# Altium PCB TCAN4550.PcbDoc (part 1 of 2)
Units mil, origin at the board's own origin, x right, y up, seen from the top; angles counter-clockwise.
Board outline 2000 x 1600 mil, 2 copper layers (Top Layer, Bottom Layer), stack 62 mil thick; 83 components, 51 nets, 217 pads, 26 vias.
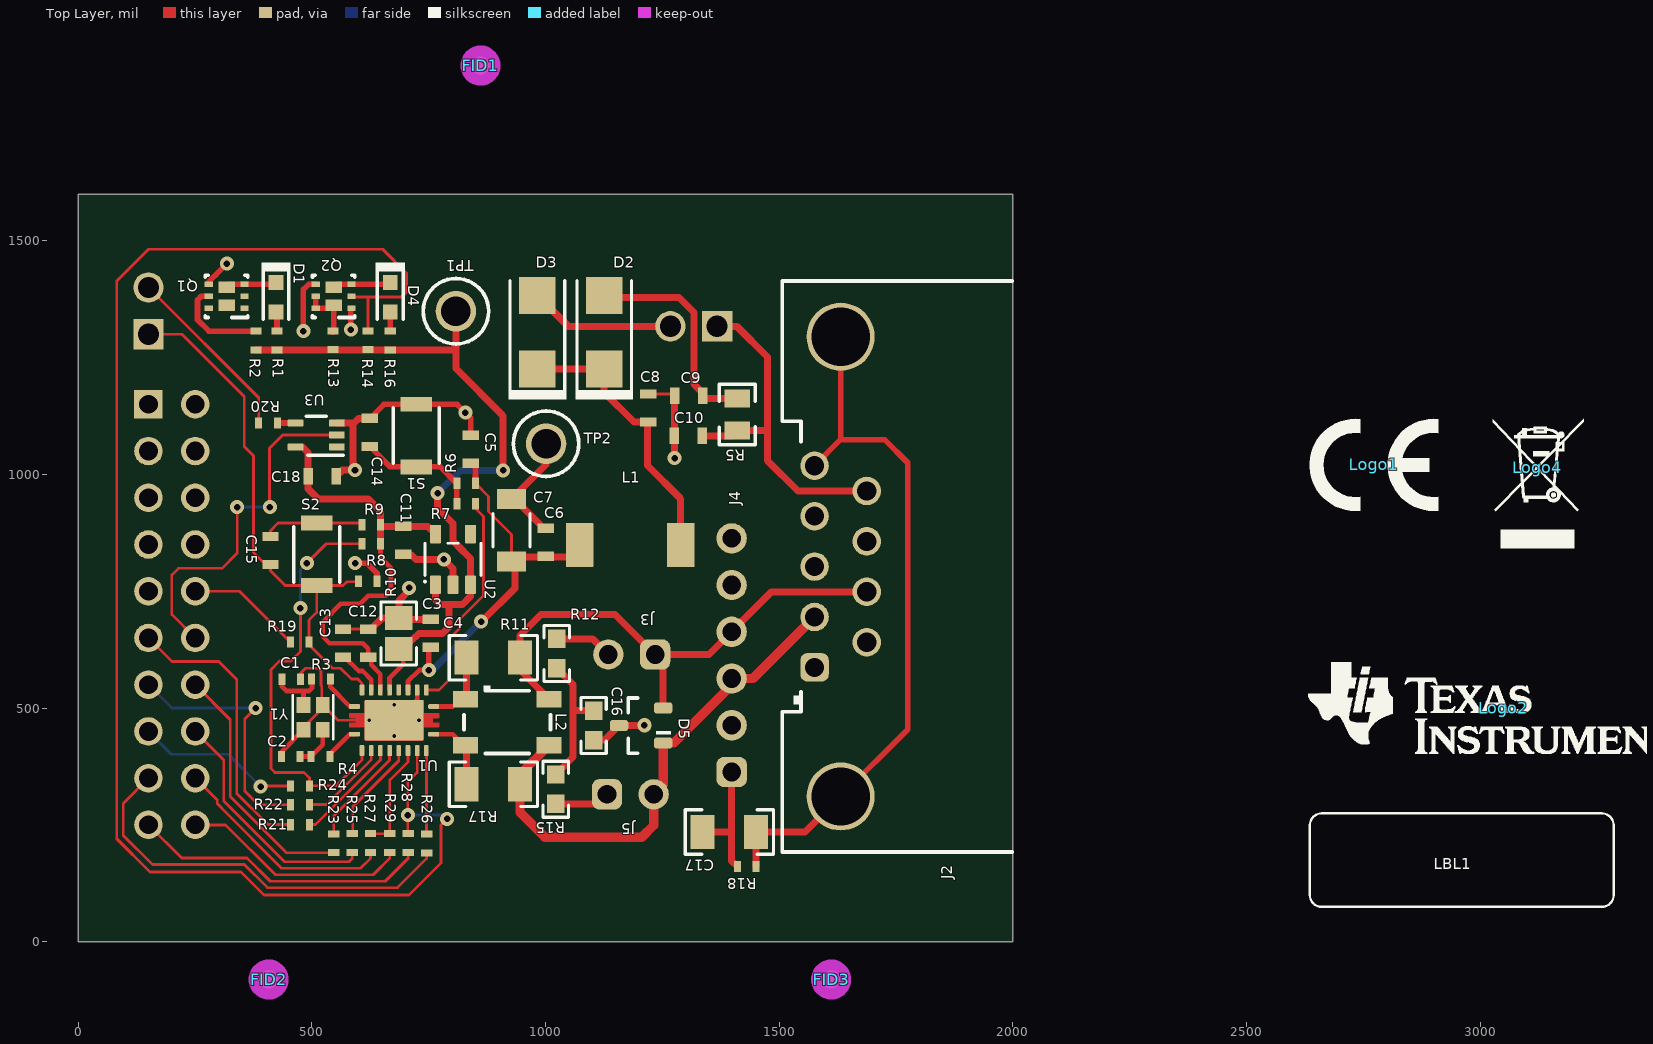
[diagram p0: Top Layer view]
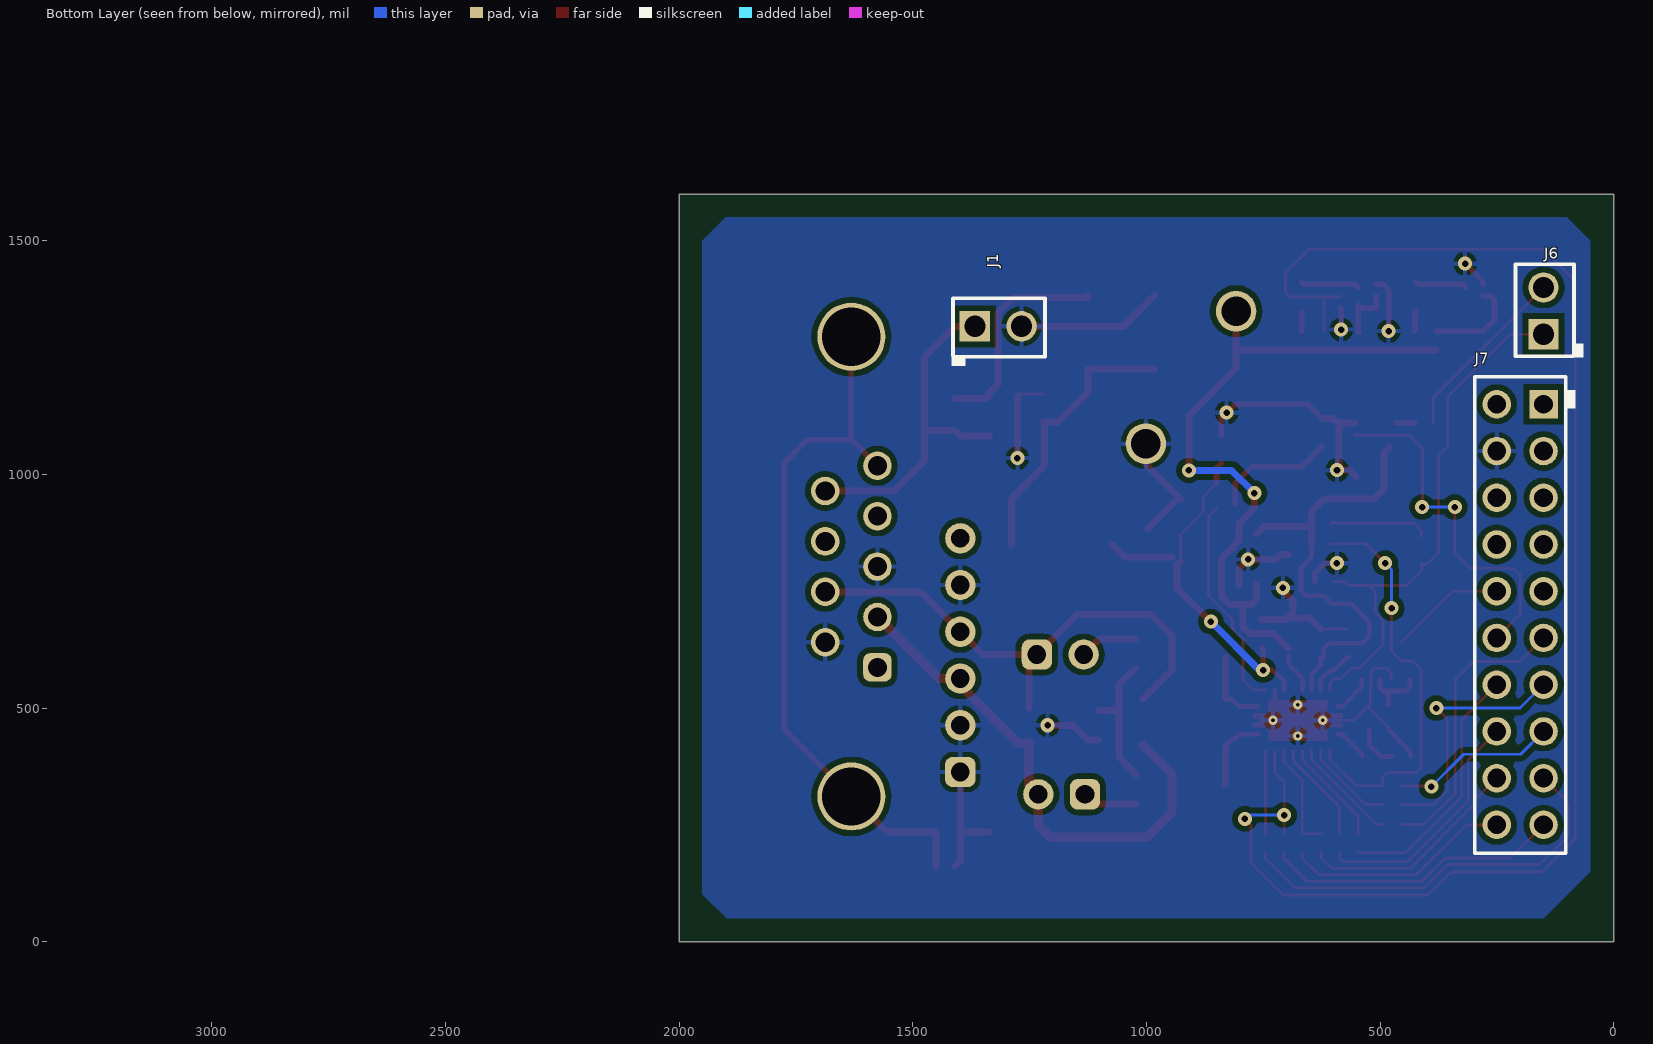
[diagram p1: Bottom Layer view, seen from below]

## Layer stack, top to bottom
Top Solder: solder mask 0.4, Solder Resist, Dk 3.5
Top Layer: signal copper 1.4
Dielectric1: core 59.2, FR-4, Dk 4.8
Bottom Layer: signal copper 1.4
Bottom Solder: solder mask 0.4, Solder Resist, Dk 3.5

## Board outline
0,0 0,1600 2000,1600 2000,0

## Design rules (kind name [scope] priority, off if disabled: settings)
AcuteAngle [All] p1: minimum=4.50000000000000E+0001 checktracksonly=FALSE
AssemblyTestPointUsage [All] p1: valid=2
BoardOutlineClearance BoardOutlineClearance_MountingHoles [OnCopper and InComponentClass('Mounting Holes')] p1: gap=39.37 ignorepadtopadclearanceinfootprint=FALSE
BoardOutlineClearance BoardOutlineClearance_Poly [OnCopper and IsPoly] p2: gap=25 ignorepadtopadclearanceinfootprint=FALSE
BoardOutlineClearance [OnCopper and Not InComponentClass('Logo') and not InComponentClass('FiducialMark') and not InRegion(1000,500,4000,800) and not InPoly] p3: gap=75 ignorepadtopadclearanceinfootprint=FALSE
Clearance Clearance_Keepouts [((IsTrack Or IsArc) And Not InPoly) And IsFree and IsKeepOut vs ((IsTrack Or IsArc) And Not InPoly) And IsFree and IsKeepOut] p1: gap=0 ignorepadtopadclearanceinfootprint=FALSE
Clearance Clearance_Poly [InPolygon] p2: gap=12 ignorepadtopadclearanceinfootprint=TRUE
Clearance Clearance_FiducialMark [IsKeepOut and InComponentClass('FiducialMark') vs IsPad and InComponentClass('FiducialMark')] p3: gap=0 ignorepadtopadclearanceinfootprint=FALSE
Clearance [All] p4: gap=7.87 ignorepadtopadclearanceinfootprint=TRUE
ComponentClearance ComponentClearance_MountingHoles_FiducialMarks [InComponentClass('Mounting Holes') vs InComponentClass('FiducialMark')] p1: gap=50 collisioncheckmode=3 verticalgap=10 showdistances=FALSE
ComponentClearance ComponentClearance_Shunt [InComponentClass('Header') vs InComponentClass('Shunt')] p2: gap=0 collisioncheckmode=3 verticalgap=0 showdistances=FALSE
ComponentClearance ComponentClearance_Logo [InComponentClass('Logo')] p3: gap=50 collisioncheckmode=3 verticalgap=10 showdistances=FALSE
ComponentClearance ComponentClearance_ScrewToNut [(HasFootprint('NY PMS 440 0025 PH')) vs (HasFootprint('Keystone_1902C'))] p4: gap=5 collisioncheckmode=3 verticalgap=10 showdistances=FALSE
ComponentClearance ComponentClearance_MountingHoles [InComponentClass('Mounting Holes')] p5: gap=250 collisioncheckmode=3 verticalgap=100000 showdistances=FALSE
ComponentClearance ComponentClearance_SmallPassives [HasFootprint('0201*') or HasFootprint('0402*') or HasFootprint('0508') or HasFootprint('0603*') or HasFootprint('0612') or HasFootprint('0805*') or HasFootprint('0815*') or HasFootprint('0830*') or HasFootprint('1206*') or HasFootprint('1210*') or HasFootprint('1808*') or HasFootprint('1812*') or HasFootprint('1825*') or HasFootprint('2010*') or HasFootprint('2220*') or HasFootprint('2225*') or HasFootprint('2512*') or HasFootprint('2728*') or HasFootprint('3518*') vs HasFootprint('0201*') or HasFootprint('0402*') or HasFootprint('0508') or HasFootprint('0603*') or HasFootprint('0612') or HasFootprint('0805*') or HasFootprint('0815*') or HasFootprint('0830*') or HasFootprint('1206*') or HasFootprint('1210*') or HasFootprint('1808*') or HasFootprint('1812*') or HasFootprint('1825*') or HasFootprint('2010*') or HasFootprint('2220*') or HasFootprint('2225*') or HasFootprint('2512*') or HasFootprint('2728*') or HasFootprint('3518*')] p6: gap=14.96 collisioncheckmode=3 verticalgap=10 showdistances=FALSE
ComponentClearance ComponentClearance_THtoSMT [IsThruComponent vs IsSMTComponent] p7: gap=40 collisioncheckmode=3 verticalgap=30 showdistances=FALSE
ComponentClearance ComponentClearance_THtoTH [IsThruComponent vs IsThruComponent] p8: gap=30 collisioncheckmode=3 verticalgap=30 showdistances=FALSE
ComponentClearance [All] p9: gap=30 collisioncheckmode=3 verticalgap=10 showdistances=FALSE
DiffPairsRouting [All] p1: maxlimit=100 minlimit=10 mostfreqgap=10 toplayer_minwidth=15 toplayer_maxwidth=15 toplayer_prefwidth=15 bottomlayer_minwidth=15 bottomlayer_maxwidth=15 bottomlayer_prefwidth=15 maxuncoupledlength=1000
FabricationTestPointUsage TestPointUsage [All] p1: valid=2 allowmultiple=FALSE
FabricationTestpoint Testpoint [All] p1: side=3 testpointundercomponent=TRUE minsize=40 maxsize=100 preferedsize=60 minholesize=0 maxholesize=40 preferedholesize=32 testpointgrid=1 allowsidetop=TRUE allowsidebottom=TRUE usegrid=TRUE gridtolerance=0.01
FanoutControl Fanout_LCC [IsLCC] p1: bgadir=Out bgaviamode=Centered fanoutstyle=Auto fanoutdirection=Alternating viagrid=1 // Fanout_LCC (Default Rule)
FanoutControl Fanout_BGA [IsBGA] p2: bgadir=Out bgaviamode=Centered fanoutstyle=Auto fanoutdirection=Alternating viagrid=1 // Fanout_BGA (Default Rule)
FanoutControl Fanout_Default [All] p4: bgadir=Out bgaviamode=Centered fanoutstyle=Auto fanoutdirection=Alternating viagrid=1 // Fanout_Default (Default Rule)
FanoutControl Fanout_Small [(CompPinCount < 5)] p5: bgadir=Out bgaviamode=Centered fanoutstyle=Auto fanoutdirection=OutThenIn viagrid=1 // Fanout_Small (Default Rule)
HoleSize [All] p1: absolutevalues=TRUE maxlimit=251 minlimit=7.87 maxpercent=80.000 minpercent=20.000
MinimumAnnularRing MinimumAnnularRing_ThermalPadVias [IsVia and InAnyComponent] p1: minimumring=5.91
MinimumAnnularRing [All] p2: minimumring=7.87
MinimumSolderMaskSliver MinimumSolderMaskSliver_Logo [InComponentClass('Logo') vs InComponentClass('Logo')] p1: minsoldermaskwidth=0.7
MinimumSolderMaskSliver [All] p2: minsoldermaskwidth=3.94
PlaneConnect [All] p1: planeconnectstyle=Relief reliefexpansion=10 reliefentries=4 reliefconductorwidth=10 reliefairgap=10
PolygonConnect [All] p1: connectstyle=Relief reliefconductorwidth=10 reliefentries=4 polygonreliefangle="90 Angle" airgapwidth=10
RoutingVias ThermalPadVias [IsVia and InAnyComponent] p1: holewidth=7.87 width=19.68 viastyle="Through Hole" minholewidth=7.87 minwidth=19.68 maxholewidth=12.99 maxwidth=23.62
RoutingVias [All] p2: holewidth=16 width=34 viastyle="Through Hole" minholewidth=7.87 minwidth=26 maxholewidth=40 maxwidth=65
SilkToBoardRegionClearance [Not ((IsComment or IsDesignator) And (Hide <> 'False')) and not InRegion(1000,500,4000,800)] p1:
SilkToSilkClearance SilkToSilkClearance_Pb-FreeLogo [(HasFootprint('Pb-Free_Overlay_Medium') OR HasFootprint('Pb-Free_Overlay_Small')) vs (HasFootprint('Pb-Free_Overlay_Medium') OR HasFootprint('Pb-Free_Overlay_Small'))] p1: silktosilkclearance=0
SilkToSilkClearance [All] p2: silktosilkclearance=3.94
SilkToSolderMaskClearance SilkToComponentPadClearance [(IsPad or IsFill or IsRegion) and InAnycomponent] p1: minsilkscreentomaskgap=5 clearancetoexposedcopper=TRUE
SilkToSolderMaskClearance "Silk to Solder Mask Opening" [All] p2: minsilkscreentomaskgap=3.94 clearancetoexposedcopper=FALSE
SolderMaskExpansion [All] p1: expansion=1.97
UnRoutedNet [All] p1: checkbadconnections=TRUE
Width [All] p1: maxlimit=100 minlimit=6 preferedwidth=10 checkconnectedcopper=TRUE
14 further rules are at their usual default settings.

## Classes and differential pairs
component class tcan4550_EVT: C1 C2 C3 C4 C5 C6 C7 C8 C9 C10 C11 C12 C13 C14 C15 C16 C17 C18 D1 D2 D3 D4 D5 J1 J2 J3 J4 J5 J6 J7 L1 L2 Q1 Q2 R1 R2 R3 R4 R5 R6 R7 R8 R9 R10 R11 R12 R13 R14 R15 R16 R17 R18 R19 R20 R21 R22 R23 R24 R25 R26 R27 R28 R29 S1 S2 TP1 TP2 TP3 U1 U2 U3 Y1
component class Header: J3 J4 J5
component class Logo: Logo2
component class Hardware: FID1 FID2 FID3 LBL1 Logo1 Logo2 Logo3 Logo4 ZZ1 ZZ2 ZZ3 ZZ4
component class FiducialMark: FID1 FID2 FID3
component class AssemblyNote: ZZ1 ZZ2 ZZ3 ZZ4
component class Label: LBL1

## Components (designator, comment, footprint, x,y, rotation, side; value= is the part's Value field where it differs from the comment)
C1 "CC0402DRNPO9BN8R0" 0402S 455.89,561.49 r0 top value=8pF
C2 "CC0402DRNPO9BN8R0" 0402S 454.24,396.43 r180 top value=8pF
C3 "CL21B106KOQNNNE" 0805 685.69,659.54 r90 top value=10uF
C4 "CGA3E2X7R1H104K080AA" 0603S 753.8,659.75 r90 top value=0.1uF
C5 "CGA3E2X7R1H104K080AA" 0603S 840,1054 r90 top value=0.1uF
C6 "UMK107AB7105KA-T" 0603S 1000,855 r90 top value=1uF
C7 "CL31B106KBHNNNE" 1206_180 927,880.43 r90 top value=10uF
C8 "CGA3E2X7R2A102K080AA" 0603S 1220,1142.16 r90 top value=1000pF
C9 "CGA3E2X7R2A102K080AA" 0603S 1306.31,1168.1 r180 top value=1000pF
C10 "CGA3E2X7R2A102K080AA" 0603S 1305.54,1082.57 r180 top value=1000pF
C11 "CGA3E2X7R1H104K080AA" 0603S 695.33,859 r270 top value=0.1uF
C12 "CGA3E2X7R1H104K080AA" 0603S 620.73,638.9 r90 top value=0.1uF
C13 "C0603C334K4RACTU" 0603S 566.37,638.9 r90 top value=0.33uF
C14 "06035A101JAT2A" 0603S 623.78,1089.86 r90 top value=100pF
C15 "06035A101JAT2A" 0603S 411.13,837.12 r90 top value=100pF
C16 "06031C472KAT2A" 0603 1102.8,462.74 r90 top value=4700pF
C17 "12061C103JAT2A" 1206 1393.15,234.83 r180 top value=0.01uF
C18 "CGA3E2X7R1H104K080AA" 0603S 521.66,996 r0 top value=0.1uF
D1 "150060GS75000" WL-SMCW_GREEN 422.94,1379.27 r270 top value=Green
D2 "MBRA140T3G" SMA 1125.44,1304.41 r90 top value=40V
D3 "3SMAJ5936B-TP" SMA 982.21,1304.41 r90 top value=30V
D4 "150060BS75000" WL-SMCW_Blue 667.44,1379.27 r270 top value=Blue
D5 "PESD1CAN,215" SOT-23 1204.42,462.6 r180 top value=24V
FID1 "Fiducial" Fiducial10-20 860.59,1875 r0 top
FID2 "Fiducial" Fiducial10-20 407.24,-81 r0 top
FID3 "Fiducial" Fiducial10-20 1611.14,-81 r0 top
J1 "SSW-101-23-F-D" Samtec_SSW-101-23-x-D 1317,1317 r90 bottom
J2 "5747840-5" TE_5747840-5 2006.81,802.75 r90 top
J3 "TSW-102-07-G-S" TSW-102-07-G-S 1184.31,614.55 r180 top
J4 "TSW-106-07-G-S" TSW-106-07-G-S 1398.15,613.19 r90 top
J5 "TSW-102-07-G-S" TSW-102-07-G-S 1181.27,315.3 r0 top
J6 "SSW-101-23-F-D" Samtec_SSW-101-23-x-D 150,1350 r0 bottom
J7 "ESQ-110-13-T-D-LL" Samtec_ESQ-110-13-x-D-LL 200,700 r270 bottom
L1 "B82462A4472M000" B82462A4 1180.91,849 r0 top value=4.7uH
L2 "ACT45B-101-2P-TL003" ACT45B 917.96,469.83 r0 top value=100uH
LBL1 "THT-14-423-10" Label_650x200 2960.7,174.57 r0 top
Logo1 "CE Mark" CE_Mark_5mm 2772.7,1020.19 r0 top
Logo2 "Texas Instruments" TI_Stacked_Overlay_Small 3050,500 r0 top
Logo3 "FCC disclaimer" FCC_disclaimer 875.88,2000 r0 top
Logo4 "WEEE logo" WEEE_Minimum 3122.7,1014.51 r0 top
Q1 "CSD85301Q2" DQK0006B 317.15,1381.26 r180 top value=20V
Q2 "CSD85301Q2" DQK0006B 546.38,1381.26 r180 top value=20V
R1 "RC0402FR-0710KL" 0402S 425,1286.7 r270 top value=10.0k
R2 "RC0402FR-0710KL" 0402S 380,1286.7 r270 top value=10.0k
R3 "RC0402JR-070RL" 0402S 519.38,561.86 r180 top value=0
R4 "RC0402JR-070RL" 0402S 518.14,396.43 r180 top value=0
R5 "5106" 5106 1410.15,1128.75 r270 top value=0
R6 "ERJ-2RKF3301X" 0402S 829.89,981 r0 top value=3.30k
R7 "CRCW040233K2FKED" 0402S 830,937.08 r0 top value=33.2k
R8 "RC0402FR-0710KL" 0402S 626.63,851.58 r0 top value=10.0k
R9 "RC0402FR-071KL" 0402S 626.63,892.48 r0 top value=1.00k
R10 "RC1005F104CS" 0402S 619,771.44 r180 top value=100k
R11 "ERJ-8GEY0R00V" 1206 887.96,607.75 r0 top value=0
R12 "RC0603FR-0760R4L" 0603 1023.79,616.61 r90 top value=60.4
R13 "RC0402FR-0710KL" 0402S 545,1287 r270 top value=10.0k
R14 "RC0402FR-0710KL" 0402S 620,1287 r270 top value=10.0k
R15 "RC0603FR-0760R4L" 0603 1021.72,326.36 r90 top value=60.4
R16 "RC0402FR-071KL" 0402S 667.44,1286.7 r270 top value=1.00k
R17 "ERJ-8GEY0R00V" 1206 887.96,336.88 r0 top value=0
R18 "ERJ-2RKF1004X" 0402S 1430.51,160.74 r0 top value=1.00Meg
R19 "RC0402JR-070RL" 0402S 473.57,641.55 r0 top value=0
R20 "RC0402FR-0710KL" 0402S 406,1110 r0 top value=10.0k
R21 "RC0402JR-070RL" 0402S 474.34,250 r180 top value=0
R22 "RC0402JR-070RL" 0402S 474.34,293.12 r180 top value=0
R23 "RC0402JR-070RL" 0402S 546.38,210.41 r90 top value=0
R24 "RC0402JR-070RL" 0402S 474.34,333.14 r180 top value=0
R25 "RC0402JR-070RL" 0402S 586.17,211.16 r90 top value=0
R26 "RC0402JR-070RL" 0402S 745.44,210 r270 top value=0
R27 "RC0402JR-070RL" 0402S 625,211.17 r90 top value=0
R28 "RC0402JR-070RL" 0402S 706.04,211.17 r270 top value=0
R29 "RC0402JR-070RL" 0402S 666.55,211.17 r90 top value=0
S1 "B3U-1000P" SW_B3U-1000P 722.89,1083.01 r270 top
S2 "B3U-1000P" SW_B3U-1000P 510,829 r270 top
TP1 "5010" Keystone5010 808,1349.3 r180 top (schematic designator TP2)
TP2 "5011" Keystone5011 1001,1065.75 r180 top (schematic designator TP3)
U1 "TCAN4550RGYRQ1" RGY0020C 675.85,473.77 r90 top
U2 "TPS73433TDDCRQ1" DDC0005A_N 801.82,818 r90 top
U3 "SN74AUP1T04DCKR" DCK0005A_N 509.04,1084.41 r180 top
Y1 "NX2016SA-40M-STD-CZS-3" XTAL_NX2016SA 502.33,480.01 r270 top
ZZ1 "This Assembly Note is for PCB labels only" AssemblyNoteLabel 185,3938 r0 top
ZZ2 "These assemblies are ESD sensitive, ESD precautions shall be observed." AssemblyNote 185,3829.11 r0 top
ZZ3 "These assemblies must be clean and free from flux and all contaminants. Use of no clean flux is not acceptable." AssemblyNote 185,3740.56 r0 top
ZZ4 "These assemblies must comply with workmanship standards IPC-A-610 Class 2, unless otherwise specified." AssemblyNote 185,3652 r0 top

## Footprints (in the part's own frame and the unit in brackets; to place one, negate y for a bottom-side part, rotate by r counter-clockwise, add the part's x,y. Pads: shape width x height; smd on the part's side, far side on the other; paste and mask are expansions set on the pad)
0402S [mil] "Based on C0402S footprint from PADS legacy"
  rect 15x24 smd: 1(-20,0) 2(20,0)
  body extent -22,-12 22,12, height 24
0603 [mm] "0603 from SM-752 data"
  rect 1x0.95 smd: 1(-0.8,0) 2(0.8,0)
  silkscreen extent -1.52,-0.69 1.52,0.69, body extent -0.87,-0.47 0.87,0.47, height 1
0603S [mil]
  rect 20x35 smd: 1(-30,0) 2(30,0)
  body extent -34,-19 34,19, height 39
0805 [mm] "0805 from SM-752 data"
  rect 1.3x1.5 smd: 1(-0.85,0) 2(0.85,0)
  silkscreen extent -1.72,-0.97 1.72,0.97, body extent -1.1,-0.72 1.1,0.72, height 1.45
1206 [mm] "1206 from SM-752 data"
  rect 1.3x1.85 smd: 1(-1.45,0) 2(1.45,0)
  silkscreen extent -2.4,-1.21 2.4,1.21, body extent -1.7,-0.9 1.7,0.9, height 1.35
1206_180 [mm] "1206_180"
  rect 1.1x1.6 smd: 1(-1.7,0) 2(1.7,0)
  silkscreen extent -0.9,-1 0.9,1, body extent -1.75,-0.95 1.75,0.95, height 1.8
5106 [mm] "Keystone"
  rect 0.99x1.4 smd: 1(-0.85,0) 2(0.88,0)
  silkscreen extent -1.63,-0.97 1.65,0.97, body extent -1.06,-0.69 1.06,0.69, height 0.84
ACT45B [mm] "SMD, 4-Leads, Body 4.7 x 3.7 mm"
  rect 1.35x0.9 smd: 1(-2.275,1.25) 2(-2.275,-1.25) 3(2.275,-1.25) 4(2.275,1.25)
  silkscreen extent -2.35,-1.7 2.35,2, body extent -2.35,-1.7 2.35,1.7, height 3
AssemblyNote [mil] "Assembly Note"
AssemblyNoteLabel [mil] "Assembly Note for PCB Labels"
B82462A4 [mm] "SMD, 2-Leads, Body 6x6mm"
  rrect7% 1.5x2.4 smd: 1(-2.75,0) 2(2.75,0)
  body extent -3.1,-3.05 3.1,2.94, height 3
CE_Mark_5mm [mil] "Minimum text height for CE Mark"
  silkscreen extent -138,-98 138,98
DCK0005A_N [mm] "SOT353, 5-Leads, Body 2x1.3mm, Pitch 0.65mm, Lead Span 2.1mm, IPC Medium Density"
  rrect25% 0.85x0.4 smd: 1(-1.125,0.65) 2(-1.125,0) 3(-1.125,-0.65) 4(1.125,-0.65) 5(1.125,0.65)
  silkscreen extent -1.48,-1.02 0.55,1.1, body extent -1.14,-1 1.14,1, height 0.95
DDC0005A_N [mm]
  rrect17% 1x0.6 smd: 1(-1.375,0.95) 2(-1.375,0) 3(-1.375,-0.95) 4(1.375,-0.95) 5(1.375,0.95)
  silkscreen extent -1.25,-1.52 0.88,1.57, body extent -1.41,-1.45 1.41,1.45, height 1.1
DQK0006B [mm] "TI"
  rect 0.45x0.3 smd: 1(-0.975,0.65) 2(-0.975,0) 3(-0.975,-0.65) 4(0.975,-0.65) 5(0.975,0) 6(0.975,0.65)
  rect 0.9x0.625 smd paste-0.025: 7(0,0.488) 8(0,-0.488)
  silkscreen extent -1.15,-1.15 1.15,1.15, body extent -1.05,-1.05 1.05,1.05, height 0.8
FCC_disclaimer [mil]
Fiducial10-20 [mm]
  round 1 smd mask+0.5: 1(0,0)
  Top Layer keep-out circle w1.178: c0,0 r0.5
Keystone5010 [mil] "Keystone Multipurpose loops"
  round 87 hole 63: 1(0,0)
  silkscreen extent -70,-70 70,70, body extent -63,-63 63,62, height 319
Keystone5011 [mil] "Keystone Multipurpose loops"
  round 87 hole 63: 1(0,0)
  silkscreen extent -70,-70 70,70, body extent -63,-63 63,62, height 319
Label_650x200 [mil] "Thermal Transfer Label"
  round 1 on Mech13: 0(0,0)
  silkscreen extent -325,-100 325,100, body extent -325,-100 325,100, height 1
RGY0020C [mm] "VQFN-20"
  rrect40% 0.25x0.6 smd: 1(-0.75,2.15) 10(-0.75,-2.15) 11(0.75,-2.15) 20(0.75,2.15)
  rrect40% 0.6x0.25 smd: 2(-1.65,1.75) 3(-1.65,1.25) 4(-1.65,0.75) 5(-1.65,0.25) 6(-1.65,-0.25) 7(-1.65,-0.75) 8(-1.65,-1.25) 9(-1.65,-1.75) 12(1.65,-1.75) 13(1.65,-1.25) 14(1.65,-0.75) 15(1.65,-0.25) 16(1.65,0.25) 17(1.65,0.75) 18(1.65,1.25) 19(1.65,1.75)
  rrect5% 2.2x3.2 smd paste-1.4: 21(0,0)
  Top Layer region: -0.375,-1.6 -1.05,-1.6 -1.069,-1.596 -1.085,-1.585 -1.096,-1.569 -1.1,-1.55 -1.1,-1.55 -1.1,1.55 -1.096,1.569 -1.085,1.585 -1.069,1.596 -1.05,1.6 -1.05,1.6 -0.375,1.6 -0.375,2.4 -0.371,2.419 -0.36,2.435 -0.344,2.446 -0.325,2.45 -0.325,2.45 -0.175,2.45 -0.156,2.446 -0.14,2.435 -0.129,2.419 -0.125,2.4 -0.125,2.4 -0.125,2.1 0.125,2.1 0.125,2.4 0.129,2.419 0.14,2.435 0.156,2.446 0.175,2.45 0.175,2.45 0.325,2.45 0.344,2.446 0.36,2.435 0.371,2.419 0.375,2.4 0.375,2.4 0.375,1.6 1.05,1.6 1.069,1.596 1.085,1.585 1.096,1.569 1.1,1.55 1.1,1.55 1.1,-1.55 1.096,-1.569 1.085,-1.585 1.069,-1.596 1.05,-1.6 1.05,-1.6 0.375,-1.6 0.375,-2.4 0.371,-2.419 0.36,-2.435 0.344,-2.446 0.325,-2.45 0.325,-2.45 0.325,-2.45 0.175,-2.45 0.175,-2.45 0.156,-2.446 0.14,-2.435 0.129,-2.419 0.125,-2.4 0.125,-2.4 0.125,-2.1 -0.125,-2.1 -0.125,-2.4 -0.129,-2.419 -0.14,-2.435 -0.156,-2.446 -0.175,-2.45 -0.175,-2.45 -0.175,-2.45 -0.325,-2.45 -0.325,-2.45 -0.344,-2.446 -0.36,-2.435 -0.371,-2.419 -0.375,-2.4 -0.375,-2.4
  body extent -1.75,-2.25 1.75,2.25, height 1
Samtec_ESQ-110-13-x-D-LL [mm] "Receptacle, 2.54mm, 10x2, TH"
  rect 1.55x1.55 hole 1.02: 1(-11.43,1.27)
  round 1.55 hole 1.02: 2(-11.43,-1.27) 3(-8.89,1.27) 4(-8.89,-1.27) 5(-6.35,1.27) 6(-6.35,-1.27) 7(-3.81,1.27) 8(-3.81,-1.27) 9(-1.27,1.27) 10(-1.27,-1.27) 11(1.27,1.27) 12(1.27,-1.27) 13(3.81,1.27) 14(3.81,-1.27) 15(6.35,1.27) 16(6.35,-1.27) 17(8.89,1.27) 18(8.89,-1.27) 19(11.43,1.27) 20(11.43,-1.27)
  silkscreen extent -12.93,-2.48 12.97,3, body extent -12.93,-2.54 12.98,2.54, height 11.06
Samtec_SSW-101-23-x-D [mm] "SAMTEC"
  rect 1.65x1.65 hole 1.15: 1(0,1.27)
  round 1.65 hole 1.15: 2(0,-1.27)
  silkscreen extent -2.16,-2.54 1.52,2.54, body extent -1.52,-2.49 1.52,2.46, height 8.59
SMA [mm] "Molded Diode, 2-Leads, Body 4.3x2.6mm, IPC Medium Density, based on OnSemi component dimensions and land pattern"
  rect 2x2 smd: 1(-2,0) 2(2,0)
  silkscreen extent -3.66,-1.57 2.79,1.57, body extent -2.6,-1.3 2.6,1.3, height 2.42
SOT-23 [mm] "SOT23, 3-Leads, Body 2.9x1.3mm, Pitch 0.95mm, Lead Span 2.5mm, IPC Medium Density"
  rrect50% 1x0.6 smd: 1(-1.2,0.95) 2(-1.2,-0.95) 3(1.2,0)
  silkscreen extent -1.63,-1.5 0.7,1.5, body extent -1.16,-1.45 1.21,1.45, height 1
SW_B3U-1000P [mm] "OMRON"
  rect 0.8x1.7 smd: 1(-1.7,0) 2(1.7,0)
  silkscreen extent -1.5,-1.25 1.5,1.25, body extent -1.5,-1.25 1.5,1.25, height 1.75
TE_5747840-5 [mm] "D-Sub, 2.74mm, 9 Position, R/A, TH"
  rrect50% 1.55x1.55 hole 1.04: 1(-5.48,10.954)
  round 1.55 hole 1.04: 2(-2.74,10.954) 3(0,10.954) 4(2.74,10.954) 5(5.48,10.954) 6(-4.11,8.114) 7(-1.37,8.114) 8(1.37,8.114) 9(4.11,8.114)
  round 3.7 hole 3.17: 10(12.495,9.534) 11(-12.495,9.534)
  silkscreen extent -15.52,0.2 15.52,12.71, body extent -15.52,-5.89 15.52,12.71, height 12.55
TI_Stacked_Overlay_Small [mil]
  silkscreen extent -418,-98 418,98
TSW-102-07-G-S [mm] "Samtec 100mil, 1x2, 230 mil above insulator"
  rrect50% 1.65x1.65 hole 1.016: 1(-1.27,0)
  round 1.65 hole 1.016: 2(1.27,0)
  body extent -2.54,-1.27 2.54,1.27, height 8.38
TSW-106-07-G-S [mm] "Samtec 100mil, 1x6, 230 mil above insulator"
  rrect50% 1.65x1.65 hole 1.016: 1(-6.35,0)
  round 1.65 hole 1.016: 2(-3.81,0) 3(-1.27,0) 4(1.27,0) 5(3.81,0) 6(6.35,0)
  body extent -7.62,-1.27 7.62,1.27, height 8.38
WEEE_Minimum [mil] "WEEElie bin"
  silkscreen extent -95,-172 99,104
WL-SMCW_Blue [mm] "SMD, 2-Leads, Body 1.6x0.8mm"
  rect 0.8x0.8 smd: 1(-0.8,0) 2(0.8,0)
  silkscreen extent -1.9,-0.8 1.2,0.8, body extent -0.85,-0.45 0.85,0.45, height 0.8
WL-SMCW_GREEN [mm] "WURTH"
  rect 0.8x0.8 smd: 1(-0.8,0) 2(0.8,0)
  silkscreen extent -1.9,-0.8 1.2,0.8, body extent -0.85,-0.45 0.85,0.45, height 0.8
XTAL_NX2016SA [mm] "2.0 x 1.6 x 0.45mm Crystal"
  rect 0.85x0.75 smd mask+0.076: 1(-0.675,-0.525) 2(0.675,-0.525) 3(0.675,0.525) 4(-0.675,0.525)
  silkscreen extent -1.2,-1.1 1.2,1.1, body extent -1,-0.8 1,0.8, height 0.51

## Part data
C1 C2: library part CMP-0860185-1, "CAP, CERM, 8 pF, 50 V,+/- 6.25%, C0G/NP0, 0402", Cap_Case=0402, Manufacturer=Yageo, TempCo=C0G/NP0, Tolerance_%=6.25%, Value2=50V, ValueDisplayed=8pF
C3: library part CMP-0007995-2, "CAP, CERM, 10 uF, 16 V, +/- 10%, X7R, 0805", Cap_Case=0805, Manufacturer="Samsung Electro-Mechanics", TempCo=X7R, Tolerance_%=10%, Value1=Unknown, Value2=16V, ValueDisplayed=10uF
C4 C5 C11 C12 C18: library part CMP-0007078-4, "CAP, CERM, 0.1 uF, 50 V, +/- 10%, X7R, AEC-Q200 Grade 1, 0603", Cap_Case=0603, Manufacturer=TDK, Supplier Part Number 1=445-5666-1-ND, TempCo=X7R, Tolerance_%=10%, Value1="0.0296 ohm", Value2=50V, ValueDisplayed=0.1uF
C6: library part CMP-0007508-5, "CAP, CERM, 1 uF, 50 V, +/- 10%, X7R, 0603", Cap_Case=0603, Manufacturer="Taiyo Yuden", Supplier Part Number 1=587-3247-1-ND, TempCo=X7R, Tolerance_%=10%, Value1=Unknown, Value2=50V, ValueDisplayed=1uF
C7: library part CMP-0008802-2, "CAP, CERM, 10 uF, 50 V, +/- 10%, X7R, 1206", Cap_Case=1206, Manufacturer=Samsung, Supplier Part Number 1=1276-6767-1-ND, TempCo=X7R, Tolerance_%=10%, Value1=Unknown, Value2=50V, ValueDisplayed=10uF
C8 C9 C10: library part CMP-0007081-4, "CAP, CERM, 1000 pF, 100 V, +/- 10%, X7R, AEC-Q200 Grade 1, 0603", Cap_Case=0603, Manufacturer=TDK, Supplier Part Number 1=445-5806-1-ND, TempCo=X7R, Tolerance_%=10%, Value1="1.97137 ohm", Value2=100V, ValueDisplayed=1000pF
C13: library part CMP-0006924-4, "CAP, CERM, 0.33 uF, 16 V, +/- 10%, X7R, 0603", Cap_Case=0603, Manufacturer=Kemet, Supplier Part Number 1=399-4916-1-ND, TempCo=X7R, Tolerance_%=10%, Value1=Unknown, Value2=16V, ValueDisplayed=0.33uF
C14 C15: library part CMP-0006763-4, "CAP, CERM, 100 pF, 50 V, +/- 5%, C0G/NP0, 0603", Cap_Case=0603, Manufacturer=AVX, Supplier Part Number 1=478-1175-1-ND, TempCo=C0G/NP0, Tolerance_%=5%, Value1="0.119 ohm", Value2=50V, ValueDisplayed=100pF
C16: library part CMP-0006746-5, "CAP, CERM, 4700 pF, 100 V, +/- 10%, X7R, 0603", Cap_Case=0603, Manufacturer=AVX, Supplier Part Number 1=478-1203-1-ND, TempCo=X7R, Tolerance_%=10%, Value1="0.136 ohm", Value2=100V, ValueDisplayed=4700pF
C17: library part CMP-0008484-2, "CAP, CERM, 0.01 uF, 100 V, +/- 5%, X7R, 1206", Cap_Case=1206, Manufacturer=AVX, Supplier Part Number 1=478-3783-1-ND, TempCo=X7R, Tolerance_%=5%, Value1="0.119 ohm", Value2=100V, ValueDisplayed=0.01uF
D1: library part CMP-0002905-2, "LED, Green, SMD", Color=Green, Manufacturer="Wurth Elektronik", Value1=W, Value2=3.2V
D2: library part CMP-0028550-2, "Diode, Schottky, 40 V, 1 A, SMA", Manufacturer="ON Semiconductor", Value1=1A, Value2=0.55V
D3: library part CMP-0005515-4, "Diode, Zener, 30 V, 3 W, SMA", Manufacturer="Micro Commercial Components", Power_W=3W
D4: library part CMP-0002946-3, "LED, Blue, SMD", Color=Blue, Manufacturer="Wurth Elektronik", Power_TotalModule=105mW, Value1=0.105W, Value2=3.2V
D5: library part CMP-0005920-3, "Diode, TVS, Bi, 24 V, 70 Vc, AEC-Q101, SOT-23", Manufacturer="NXP Semiconductor", Value1=200W
FID1 FID2 FID3: library part CMP-0077181-1, "Fiducial mark.  There is nothing to buy or mount.", Manufacturer=N/A
J1 J6: library part CMP-0055671-1, "Receptacle, 2.54mm, 1x2, Gold, TH", Color=Black, Current_A=5.7A, Manufacturer=Samtec, Voltage_V=550V
J2: library part CMP-0054938-4, "D-Sub, 2.74mm, 9 Position, R/A, TH", Color=Black, Manufacturer="TE Connectivity", Supplier Part Number 1=A32093-ND
J3 J5: library part CMP-0075405-2, "Header, 100mil, 2x1, Gold, TH", Color=Black, Current_A=6.3A, Manufacturer=Samtec, Supplier Part Number 1=SAM1029-02-ND, Voltage_V=550V
J4: library part CMP-0075413-2, "Header, 100mil, 6x1, Gold, TH", Color=Black, Current_A=6.3A, Manufacturer=Samtec, Supplier Part Number 1=SAM1029-06-ND, Voltage_V=550V
J7: library part CMP-0075645-1, "Receptacle, 2.54mm, 10x2, Tin, TH", Current_A=5.7A, Manufacturer=Samtec, Voltage_V=550V
L1: library part CMP-0001617-1, "Inductor, Wirewound, Ferrite, 4.7 µH, 1.65 A, 0.08 ohm, AEC-Q200 Grade 0, SMD", Manufacturer=TDK, Supplier Part Number 1=495-2665-1-ND, Value1="0.08 ohm", Value2=1.65A, ValueDisplayed=4.7µH
L2: library part CMP-0062430-2, "Inductor, Ferrite, 100 uH, 0.15 A, 2 ohm, SMD", Manufacturer=TDK, Supplier Part Number 1=445-3959-1-ND, Value1="2 ohm", Value2=0.15A, ValueDisplayed=100uH
LBL1: library part CMP-0003625-1, "Thermal Transfer Printable Labels, 0.650\" W x 0.200\" H - 10,000 per roll", Manufacturer=Brady, Supplier Part Number 1=97C5133
Logo1: library part CMP-0074844-1
Logo2: library part CMP-0074838-1, "Texas Instrument Corporate Signature"
Logo3: library part CMP-0074847-1, "FCC_disclaimer"
Logo4: library part CMP-0074769-1
Q1 Q2: library part CMP-0000208-1, "MOSFET, 2-CH, N-CH, 20 V, 6.7 A, DQK0006B (WSON-6)", Alternate Manufacturer=None, Manufacturer="Texas Instruments", Supplier Part Number 1=296-40010-1-ND, Value1=0.02, Value2="4.2 nC"
R1 R2 R8 R13 R14 R20: library part CMP-0078669-1, "RES, 10.0 k, 1%, 0.063 W, 0402", Manufacturer="Yageo America", Power_W=63mW, Supplier Part Number 1=311-10.0KLRCT-ND, TempCo="100 ppm/C", Tolerance_%=1%, Value2=0.063W, Value_Code=10k0, ValueDisplayed=10.0k
R3 R4 R19 R21 R22 R23 R24 R25 R26 R27 R28 R29: library part CMP-0027004-2, "RES, 0, 5%, 0.063 W, 0402", Manufacturer="Yageo America", Power_W=63mW, Supplier Part Number 1=311-0.0JRCT-ND, TempCo="200 ppm/C", Tolerance_%=5%, Value2=0.063W, Value_Code=0000, ValueDisplayed=0
R5: library part CMP-0020833-2, "RES, 0, 1%, 0.5 W, 0805", Manufacturer=Keystone, Power_W=500mW, Supplier Part Number 1=36-5106CT-ND, TempCo=ppm/C, Tolerance_%=1%, Value2=0.5W, Value_Code=0
R6: library part CMP-0026695-1, "RES, 3.30 k, 1%, 0.1 W, AEC-Q200 Grade 0, 0402", Manufacturer=Panasonic, Power_W=100mW, Supplier Part Number 1=P3.30KLCT-ND, TempCo="100 ppm/C", Tolerance_%=1%, Value2=0.1W, Value_Code=3k30, ValueDisplayed=3.30k
R7: library part CMP-0026298-2, "RES, 33.2 k, 1%, 0.063 W, AEC-Q200 Grade 0, 0402", Manufacturer=Vishay-Dale, Power_W=63mW, Supplier Part Number 1=541-33.2KLCT-ND, TempCo="100 ppm/C", Tolerance_%=1%, Value2=0.063W, Value_Code=33k2, ValueDisplayed=33.2k
R9 R16: library part CMP-0026725-1, "RES, 1.00 k, 1%, 0.0625 W, 0402", Manufacturer="Yageo America", Power_W=62.5mW, Supplier Part Number 1=311-1.00KLRCT-ND, TempCo="100 ppm/C", Tolerance_%=1%, Value2=0.0625W, Value_Code=1k00, ValueDisplayed=1.00k
R10: library part CMP-0026745-1, "RES, 100 k, 1%, 0.063 W, 0402", Manufacturer="Samsung Electro-Mechanics", Power_W=63mW, Supplier Part Number 1=1276-3432-1-ND, TempCo="100 ppm/C", Tolerance_%=1%, Value2=0.063W, Value_Code=100k
R11 R17: library part CMP-0018748-3, "RES, 0, 5%, 0.25 W, AEC-Q200 Grade 0, 1206", Manufacturer=Panasonic, Power_W=250mW, Supplier Part Number 1=P0.0ECT-ND, TempCo="600 ppm/C", Tolerance_%=5%, Value2=0.25W, Value_Code=0000, ValueDisplayed=0
R12 R15: library part CMP-0023213-5, "RES, 60.4, 1%, 0.1 W, 0603", Manufacturer=Yageo, Power_W=100mW, Supplier Part Number 1=311-60.4HRCT-ND, TempCo="100 ppm/C", Tolerance_%=1%, Value2=0.1W, Value_Code=60R4, ValueDisplayed=60.4
R18: library part CMP-0026660-1, "RES, 1.00 M, 1%, 0.1 W, 0402", Manufacturer=Panasonic, Power_W=100mW, Supplier Part Number 1=P1.00MLCT-ND, TempCo="100 ppm/C", Tolerance_%=1%, Value2=0.1W, Value_Code=1M00, ValueDisplayed=1.00M
S1 S2: library part CMP-0002150-2, "SWITCH TACTILE SPST-NO 0.05A 12V", CurrentRating_mA=50A, Manufacturer="Omron Electronic Components", Supplier Part Number 1=SW1020CT-ND
TP1: library part CMP-0055147-1, "Test Point, Multipurpose, Red, TH", Color=Red, Manufacturer=Keystone, Supplier Part Number 1=36-5010-ND
TP2: library part CMP-0055148-1, "Test Point, Multipurpose, Black, TH", Color=Black, Manufacturer=Keystone, Supplier Part Number 1=36-5011-ND
U1: library part CMP-0065224-7, "CAN-FD Controller with Integrated Transceiver, RGY0020A (VQFN-20)", Alternate Manufacturer="Texas Instruments", Alternate PartNumber=TCAN4550RGYQ1, Operating Temperature Range="-40 to 125 C", Rating=Automotive
U2: library part CMP-0035843-1, "Single Output High PSRR LDO, 250 mA, Fixed 3.3 V Output, 2.7 to 6.5 V Input, with Low IQ, 5-pin SOT (DDC), -40 to 105 degC, Green (RoHS & no Sb/Br)", Manufacturer="Texas Instruments", Rating=Automotive
U3: library part CMP-0051651-2, "Low Power, 1.8/2.5/3.3-V Input, 3.3-V CMOS Output, Single Inverter Gate, DCK0005A, LARGE T&R", F @ Nom Voltage(Max)(Mhz)=190, Generic Part Number=SN74AUP1T04, ICC @ Nom Voltage(Max)(mA)=0.0009, Manufacturer="Texas Instruments", Operating Temperature Range(C)="-40 to 85", Rating=Catalog, tpd @ Nom Voltage(Max)(ns)=9.8,8.5,7.8, Voltage(Nom)(V)=1.8,2.5,3.3
Y1: library part CMP-0085289-1, "Crystal, 40 MHz, 10 ppm, 8 pF, AEC-Q200 Grade 0, SMD", Frequency_Fixed=40MHz, Frequency Stability="25 ppm", Frequency Tolerance="10 ppm", Load Capacitance="8 pF", Manufacturer=NDK
ZZ1: library part CMP-0003616-3
ZZ2: library part CMP-0077236-1
ZZ3: library part CMP-0077237-1
ZZ4: library part CMP-0077238-1

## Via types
v1: diameter 30, hole 14, Top Layer to Bottom Layer, 22 vias
v2: diameter 19.68, hole 7.87, Top Layer to Bottom Layer, 4 vias

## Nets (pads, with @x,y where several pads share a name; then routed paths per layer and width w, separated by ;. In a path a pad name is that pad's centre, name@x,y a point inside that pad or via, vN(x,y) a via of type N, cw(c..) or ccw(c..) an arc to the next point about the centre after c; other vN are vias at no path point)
3V3: C11.1 C12.1 C18.1 R8.2 R9.2 U1.17 U2.5 U3.5 | length 984.1
  Top Layer w10: C12.1@620.73,608.9 620.73,627.04 608.87,638.9 537.46,638.9 523,653.36 523,684 562,723 603.46,723 620.81,740.35 658,740.35 669,751.35 669,800.5 646.63,822.87 R8.2@646.63,851.58 ; C12.1@626.63,608.9 626.63,592.55 646.32,572.86 U1.17@646.32,538.73
  Top Layer w15: U3.5@480,1058.82 491.66,1047.16 C18.1@491.66,996 491.66,969.23 513,947.89 619.63,947.89 646.63,920.89 R9.2@646.63,892.48 ; R8.2@646.63,851.58 R9.2@646.63,892.48 ; U2.5@764.42,872.13 747.55,889 C11.1@695.33,889 650.11,889 R9.2@646.63,892.48
CAN_GPIO1: J7.13 R22.2 | length 547.7
  Top Layer w6: v1(379.43,500) 356,476.57 356,322.74 385.62,293.12 R22.2@454.34,293.12
  Bottom Layer w6: J7.13@150,550 200,500 v1(379.43,500)
CAN_GPO2: J7.17 R26.2 | length 878.7
  Top Layer w6: J7.17@150,350 95.92,295.92 95.92,227.6 158.52,165 355,165 404.46,115.54 683.17,115.54 745.44,177.82 R26.2@745.44,190
CAN_nINT: J7.19 R28.2 | length 638.9
  Top Layer w6: J7.19@150,250 221.13,178.87 361.13,178.87 410.58,129.42 656.87,129.42 706.04,178.58 R28.2@706.04,191.17
CAN_nWRKQ: J7.15 R24.2 | length 353.7
  Top Layer w6: v1(390,332) 391.14,333.14 R24.2@454.34,333.14
  Bottom Layer w6: J7.15@150,450 198.81,401.19 320.81,401.19 v1(390,332)
CAN_RST: C15.1 J6.1 R10.2 R19.2 S2.2 U1.19 | length 1167.9
  Top Layer w6: J6.1@150,1300 222,1300 355,1167 355,1060 375,1040 375,832.94 400.82,807.12 C15.1@411.13,807.12 411.13,793.81 442.87,762.07 S2.2@510,762.07 S2.2@523,762.07 ; R10.2@599,771.44 597.96,770.4 574.69,770.4 566.37,762.07 S2.2@523,762.07 ; U1.19@606.95,538.73 606.95,552.76 597.85,561.86 584.26,561.86 561.01,585.11 543.98,585.11 493.57,635.52 R19.2@493.57,641.55 493.57,688.24 510,704.67 510,749.07 S2.2@523,762.07
CANH: L2.1 R11.1 U1.11 | length 164.2
  Top Layer w10: U1.11@760.49,503.29 801.09,503.29 816.84,519.04 L2.1@828.4,519.04
  Top Layer w15: L2.1@828.4,519.04 830.87,521.52 R11.1@830.87,607.75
